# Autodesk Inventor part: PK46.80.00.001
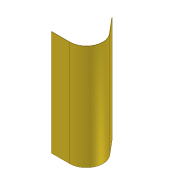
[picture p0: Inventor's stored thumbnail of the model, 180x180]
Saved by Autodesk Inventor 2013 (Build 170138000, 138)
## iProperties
Shininess: 64.0
Length Units: 11269
Angle Units: 11279
Time Units: 11290
Mass Units: 11283
Length Display Precision: 3
Angle Display Precision: 2
Compacted: True
Part Number: PK46.80.00.001
Document SubType Name: Sheet Metal
Created: 2005-01
Material: Steel, Mild
Designer: SAlex
Manufacturer: Standard
Standards Organization: Custom
Density: 7.86 g/cm^3
Flat Pattern Width: 307.983 cm
Flat Pattern Length: 316.912 cm
Flat Pattern Area: 97603.7 cm^2
Sheet Metal Rule: Default
Mass: 301208 g
Surface Area: 96512.8 cm^2
Volume: 38321.7 cm^3
Density: 0.0
Volumn: 0.0
Area: 0.0
PropertySet Name: Model Information
Control State: 0
Master: False
Checked Out: False
Checked Out Date: 2008-10-15
Last Check In Date: 2008-10-15
Author: SAlex
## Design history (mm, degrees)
node "Contour Flange1"
  sketch "Sketch1"
    geometry: L1 (0, -373.417)-(-450, -373.417); L2 (306.418, 283.698)-(-8.548, 659.06); A1 r 400 centre (0, 26.583) between (0, -373.417) and (306.418, 283.698)
    constraints: 4 end point, 2 point on circle, 2 tangent, 1 centre point, 1 horizontal, 1 other
    dimensions: "d0" = 800 diameter of A1; "d5" = 490 distance of L2.start L2.end; "d6" = 450 distance of L1.start L1.end; "d15" = 130 deg dimension on A1.centre L2.start L1.start
workplane "Work Plane1"
body "Solid1"
face "Plate1" dims "d8" = 2580, "d9" = 8 (= BendReliefWidth), "d11" = 16 (= MinimumRemnant), "d13" = 8 (= BendRadius), "d14" = 8, "Thickness" = 8
bend "Bend1" dims "d9" = 8 (= BendReliefWidth), "d10" = 4 (= BendReliefDepth), "d11" = 16 (= MinimumRemnant), "d12" = 8 (= BendRadius), "d13" = 8 (= BendRadius), "d14" = 8, "SeamGap" = 0.01, "Thickness" = 8
node "Развертка"
feature "FlatPatternExtrusion2" dims "d0" = 8 (derived)
other parameters: "BendRadius" = 8 (= Thickness), "BendReliefWidth" = 8 (= Thickness), "BendReliefDepth" = 4 (= 0.5 x Thickness), "CornerReliefSize" = 32 (= 4 x Thickness), "MinimumRemnant" = 16 (= 2 x Thickness), "TransitionRadius" = 8 (= BendRadius), "JacobiRadiusSize" = 8 (= Thickness), "GapSize" = 8 (= Thickness)
